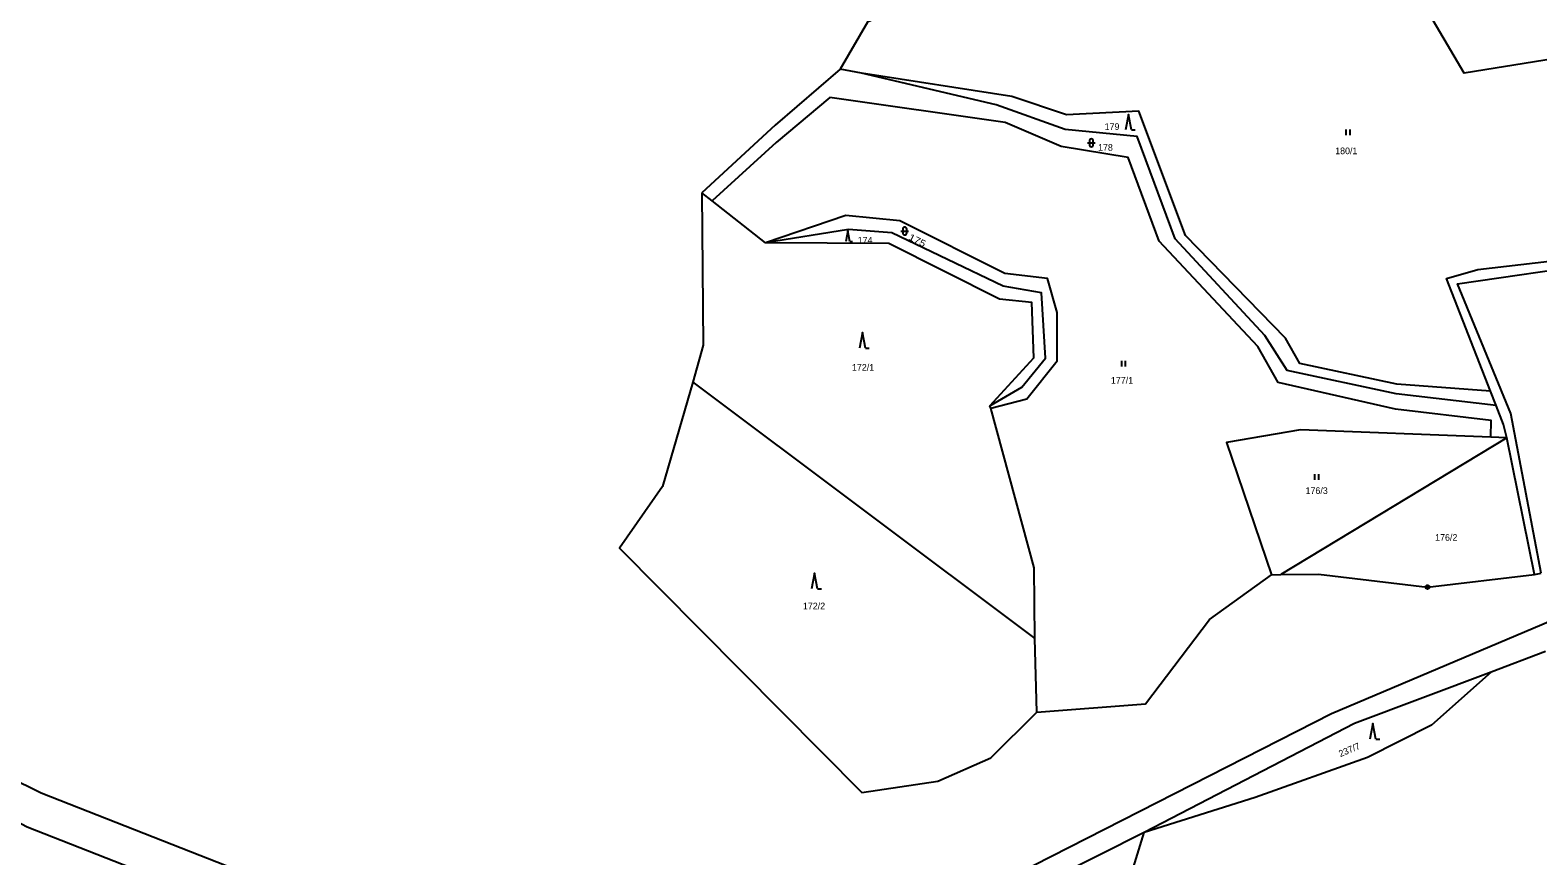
# Model space of a CAD drawing. Extents: x -632162 to -629607, y -1101195 to -1098670.
# Drawn here: x -631426.6 to -631040.8, y -1099752.9 to -1099541.5 of the extents above; entities that cross this region are included whole.
import ezdxf
from ezdxf.enums import TextEntityAlignment as Align

# ---------------------------------------------------------------- set-up
doc = ezdxf.new("R2010")
doc.units = 0
doc.header["$LTSCALE"] = 0.68
for name, color, linetype, lineweight in [('1', 7, 'Continuous', 25), ('3', 7, 'Continuous', 25), ('8', 7, 'Continuous', 25)]:
    doc.layers.add(name, color=color, linetype=linetype, lineweight=lineweight)
doc.layers.add('2', color=7, linetype='Continuous')

msp = doc.modelspace()

# ---------------------------------------------------------------- linework, layer by layer
at = {"layer": '1'}
for p, q in [((-631213.85, -1099552.5), (-631219.33, -1099551.54)), ((-631180.83, -1099638.31), (-631181.03, -1099637.65)), ((-631051.5, -1099637.62), (-631052.93, -1099633.96)), ((-631048.79, -1099645.83), (-631052.89, -1099645.66)), ((-631108.94, -1099680.93), (-631106.55, -1099680.89)), ((-631041.67, -1099680.85), (-631039.98, -1099680.51)), ((-631168.99, -1099716.07), (-631169.54, -1099697.26)), ((-631038.83, -1099700.55), (-631052.81, -1099705.81))]:
    msp.add_line(p, q, dxfattribs=at)
for points in [[(-631091.14, -1099498.92), (-631112.27, -1099499.47), (-631167.47, -1099524.35), (-631188.7, -1099534.26), (-631199.88, -1099533.92), (-631212.38, -1099539.47), (-631219.33, -1099551.54)], [(-631006.36, -1099537.27), (-631021.08, -1099546.27), (-631059.67, -1099552.5), (-631091.14, -1099498.92)], [(-631219.33, -1099551.54), (-631235.97, -1099565.83), (-631254.71, -1099583.13)], [(-631051.5, -1099637.62), (-631077.05, -1099634.59), (-631104.93, -1099628.62), (-631110.69, -1099619.68), (-631133.62, -1099594.92), (-631143.37, -1099568.73), (-631161.77, -1099566.98), (-631179.45, -1099560.63), (-631213.85, -1099552.5)], [(-631052.93, -1099633.96), (-631076.89, -1099632.14), (-631101.75, -1099626.85), (-631105.36, -1099620.4), (-631130.96, -1099594.11), (-631142.91, -1099562.23), (-631161.39, -1099563.21), (-631175.42, -1099558.54), (-631213.85, -1099552.5)], [(-631052.89, -1099645.66), (-631052.73, -1099641.46), (-631077.21, -1099638.53), (-631107.29, -1099631.71), (-631112.46, -1099622.48), (-631137.68, -1099595.56), (-631145.65, -1099574.13), (-631162.83, -1099571.28), (-631177.11, -1099565.16), (-631221.98, -1099558.77), (-631235.75, -1099570.28), (-631252.13, -1099585.21)], [(-631052.93, -1099633.96), (-631064.19, -1099605.09), (-631056.15, -1099602.76), (-631026.83, -1099599.37), (-631023.66, -1099597.58), (-631013.93, -1099598.2), (-631012.14, -1099597.76), (-631004.42, -1099560.95)], [(-631254.71, -1099583.13), (-631254.37, -1099622.11), (-631257.06, -1099631.62), (-631169.54, -1099697.26)], [(-631181.03, -1099637.65), (-631169.76, -1099625.41), (-631170.34, -1099611.27), (-631178.56, -1099610.36), (-631206.92, -1099596.16), (-631238.41, -1099595.98), (-631252.13, -1099585.21), (-631254.71, -1099583.13)], [(-631180.83, -1099638.31), (-631171.59, -1099635.92), (-631163.79, -1099626.19), (-631163.83, -1099613.81), (-631166.29, -1099605.1), (-631177.19, -1099603.83), (-631204.08, -1099590.29), (-631217.89, -1099588.98), (-631238.41, -1099595.98)], [(-631181.03, -1099637.65), (-631172.9, -1099632.92), (-631166.8, -1099625.51), (-631167.86, -1099608.72), (-631177.66, -1099607.07), (-631206.14, -1099593.36), (-631217.2, -1099592.51), (-631238.41, -1099595.98)], [(-631039.98, -1099680.51), (-631047.72, -1099639.68), (-631061.37, -1099606.43), (-631024.96, -1099601.16), (-631020.15, -1099602.42), (-630975.74, -1099617.95), (-630975.07, -1099615.11), (-630990.44, -1099603.92)], [(-631257.06, -1099631.62), (-631264.79, -1099658.29), (-631275.77, -1099674.14), (-631213.84, -1099736.66), (-631194.32, -1099733.76), (-631180.82, -1099727.78), (-631168.99, -1099716.07)], [(-631048.79, -1099645.83), (-631049.63, -1099642.43), (-631051.5, -1099637.62)], [(-631169.54, -1099697.26), (-631169.69, -1099679.14), (-631180.83, -1099638.31)], [(-631052.89, -1099645.66), (-631101.54, -1099643.8), (-631120.48, -1099647.1), (-631108.94, -1099680.93)], [(-631573.73, -1099649.04), (-631561.78, -1099657.37), (-631473.19, -1099721.18), (-631427.36, -1099745.46), (-631262.62, -1099810.08), (-631104.85, -1099904.21), (-631080.72, -1099918.6), (-630227.98, -1100408.08)], [(-631041.67, -1099680.85), (-631048.79, -1099645.83), (-631106.55, -1099680.89)], [(-631001.85, -1099672.16), (-631021.44, -1099685.96), (-631093.61, -1099716.5), (-631142.66, -1099741.51), (-631259.83, -1099801.22)], [(-631168.99, -1099716.07), (-631141.26, -1099713.95), (-631124.84, -1099692.39), (-631108.94, -1099680.93)], [(-631106.55, -1099680.89), (-631096.93, -1099680.74), (-631069.05, -1099684.07), (-631041.67, -1099680.85)], [(-631052.81, -1099705.81), (-631068.05, -1099719.43), (-631084.4, -1099727.66), (-631113.18, -1099737.94), (-631141.59, -1099746.86)], [(-631052.81, -1099705.81), (-631087.77, -1099718.96), (-631141.59, -1099746.86)], [(-631259.83, -1099801.22), (-631423.81, -1099736.81), (-631440.94, -1099728.4)], [(-631141.59, -1099746.86), (-631254.98, -1099804.01), (-631208.09, -1099803.66)], [(-631208.09, -1099803.66), (-631188.84, -1099783.64), (-631163.54, -1099776.07), (-631147.77, -1099767.07), (-631141.59, -1099746.86)]]:
    msp.add_lwpolyline(points, dxfattribs=at)
at = {"layer": '3'}
for p, q in [((-631144.83, -1099567.07), (-631143.834, -1099567.07)), ((-631089.831, -1099568.43), (-631089.831, -1099566.93)), ((-631088.83, -1099568.43), (-631088.83, -1099566.93)), ((-631156.071, -1099570.371), (-631154.069, -1099570.371)), ((-631155.571, -1099569.871), (-631155.571, -1099570.872)), ((-631154.569, -1099570.872), (-631154.569, -1099569.871)), ((-631203.821, -1099592.941), (-631201.819, -1099592.941)), ((-631203.321, -1099592.441), (-631203.321, -1099593.442)), ((-631202.319, -1099593.442), (-631202.319, -1099592.441)), ((-631216.858, -1099595.6), (-631216.19, -1099595.6)), ((-631212.88, -1099622.91), (-631211.884, -1099622.91)), ((-631147.301, -1099627.65), (-631147.301, -1099626.15)), ((-631146.3, -1099627.65), (-631146.3, -1099626.15)), ((-631097.881, -1099656.66), (-631097.881, -1099655.16)), ((-631096.88, -1099656.66), (-631096.88, -1099655.16)), ((-631225.14, -1099684.51), (-631224.144, -1099684.51)), ((-631082.28, -1099723.03), (-631081.284, -1099723.03))]:
    msp.add_line(p, q, dxfattribs=at)
for points in [[(-631144.83, -1099567.07), (-631145.58, -1099563.07), (-631146.33, -1099567.07)], [(-631216.858, -1099595.6), (-631217.36, -1099592.92), (-631217.862, -1099595.6)], [(-631212.88, -1099622.91), (-631213.63, -1099618.91), (-631214.38, -1099622.91)], [(-631225.14, -1099684.51), (-631225.89, -1099680.51), (-631226.64, -1099684.51)], [(-631082.28, -1099723.03), (-631083.03, -1099719.03), (-631083.78, -1099723.03)]]:
    msp.add_lwpolyline(points, dxfattribs=at)
for centre, start, end in [((-631155.07, -1099569.8709), 0, 180), ((-631155.07, -1099570.8709), 180, 359.98789), ((-631202.82, -1099592.4409), 0, 180), ((-631202.82, -1099593.4409), 180, 359.98789)]:
    msp.add_arc(centre, 0.5, start, end, dxfattribs=at)
at = {"layer": '8'}
for radius in [0.5, 0.0303]:
    msp.add_circle((-631069.05, -1099684.0699), radius, dxfattribs=at)

# ---------------------------------------------------------------- texts
at = {"layer": '2'}
for s, p in [('179', (-631149.779, -1099567.06)), ('178', (-631151.469, -1099572.39)), ('180/1', (-631089.84, -1099573.27)), ('174', (-631212.969, -1099596.16)), ('172/1', (-631213.49, -1099628.7)), ('177/1', (-631147.23, -1099632.01)), ('176/3', (-631097.42, -1099660.23)), ('176/2', (-631064.27, -1099672.22)), ('172/2', (-631226.03, -1099689.75))]:
    msp.add_text(s, height=1.7, dxfattribs=at).set_placement(p, align=Align.CENTER)
at = {"layer": '2', "width": 1.2}
msp.add_text('175', height=1.7, rotation=333, dxfattribs=at).set_placement((-631199.9884, -1099596.0875), align=Align.CENTER)
at = {"layer": '2'}
msp.add_text('237/7', height=1.7, rotation=23, dxfattribs=at).set_placement((-631088.7256, -1099726.4983), align=Align.CENTER)

doc.saveas('drawing.dxf')
